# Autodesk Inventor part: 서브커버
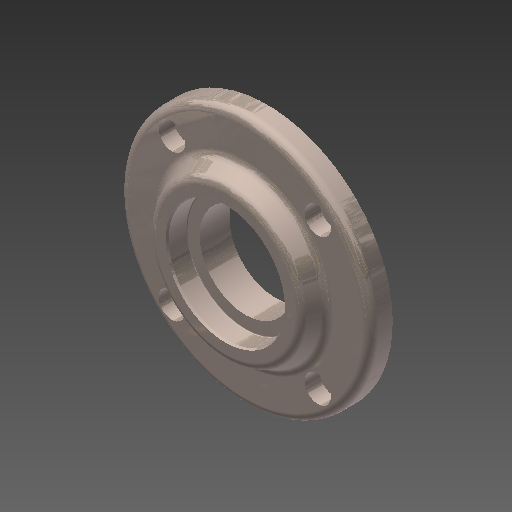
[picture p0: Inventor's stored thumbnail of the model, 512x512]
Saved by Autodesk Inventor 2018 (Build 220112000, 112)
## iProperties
Created: 2013-01
Part Number: 서브커버
Document SubType Name: Modeling
Designer: 한국산업디자인학원[gmhk.co.kr]
Density: 7.25 g/cm^3
Material: 주철
Mass: 439.929 g
Surface Area: 178.476 cm^2
Volume: 60.6798 cm^3
Appearance: 강철(1)
Author: 한국산업디자인학원[gmhk.co.kr]
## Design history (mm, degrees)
sketch "스케치2"
  geometry: L1 (-45, 0)-(0, 0); L2 (-25.784, -7)-(25.784, -7) reference; L3 (0, -7)-(0, 15); L4 (-31, -23)-(-31, 0) reference; L5 (-26.5, -7)-(-26.5, -3); L6 (-26.5, -3)-(0, -3); L7 (-26.5, -7)-(-31, -7); L8 (-31, 0)-(-45, 0); L9 (-45, 0)-(-45, 8); L10 (-45, 8)-(-30, 8); L11 (-30, 8)-(-26.736, 15); L12 (-26.736, 15)-(0, 15)
  constraints: 25 end point, 6 perpendicular, 3 point on line, 1 collinear, 1 horizontal, 1 midpoint, 1 parallel, 1 vertical, 3 other
  dimensions: "d0" = 53 diameter of L5 L3; "d1" = 4 distance between parallel lines of L6 L2; "d2" = 8 distance between parallel lines of L10 L1; "d3" = 7 distance between parallel lines of L12 L10; "d4" = 60 diameter of L10.end L3; "d5" = 115 deg angle of L11 L10; "d27" = 90 diameter of L9 L3
revolve "회전1" sketch "스케치2" stored, may be unused: angle "d6" = 90 deg
hole "구멍1" diameter "d9" = 33; stored, may be unused: countersink angle "d13" = 90 deg, drill point angle "d15" = 118 deg; dims "d10" = 6, "d11" = 42, "d12" = 7.3, "d14" = 8, "d38" = 10, "d39" = 10
fillet "모깎기1" dims "d16" = 3
chamfer "모따기1" distance "d17" = 0.7; stored, may be unused: second distance "d18" = 2, angle "d19" = 30 deg
sketch "스케치3"
  geometry: C1 r 2.067 at (26.163, 26.163) reference; 1 further point
hole "구멍2" sketch "스케치3" at (26.163, 26.163) diameter "d20" = 5.4; stored, may be unused: countersink angle "d24" = 90 deg, drill point angle "d26" = 118 deg; dims "d21" = 6, "d22" = 9.5, "d23" = 5.5, "d25" = 8
fillet "모깎기2" dims "d31" = 0.3
fillet "모깎기3" dims "d32" = 3
chamfer "모따기2" distance "d35" = 1; stored, may be unused: second distance "d36" = 2, angle "d37" = 45 deg
node "솔리드1"
pattern_circular "원형 패턴1" dims angle "d29" = 360 deg
node "참조3"
